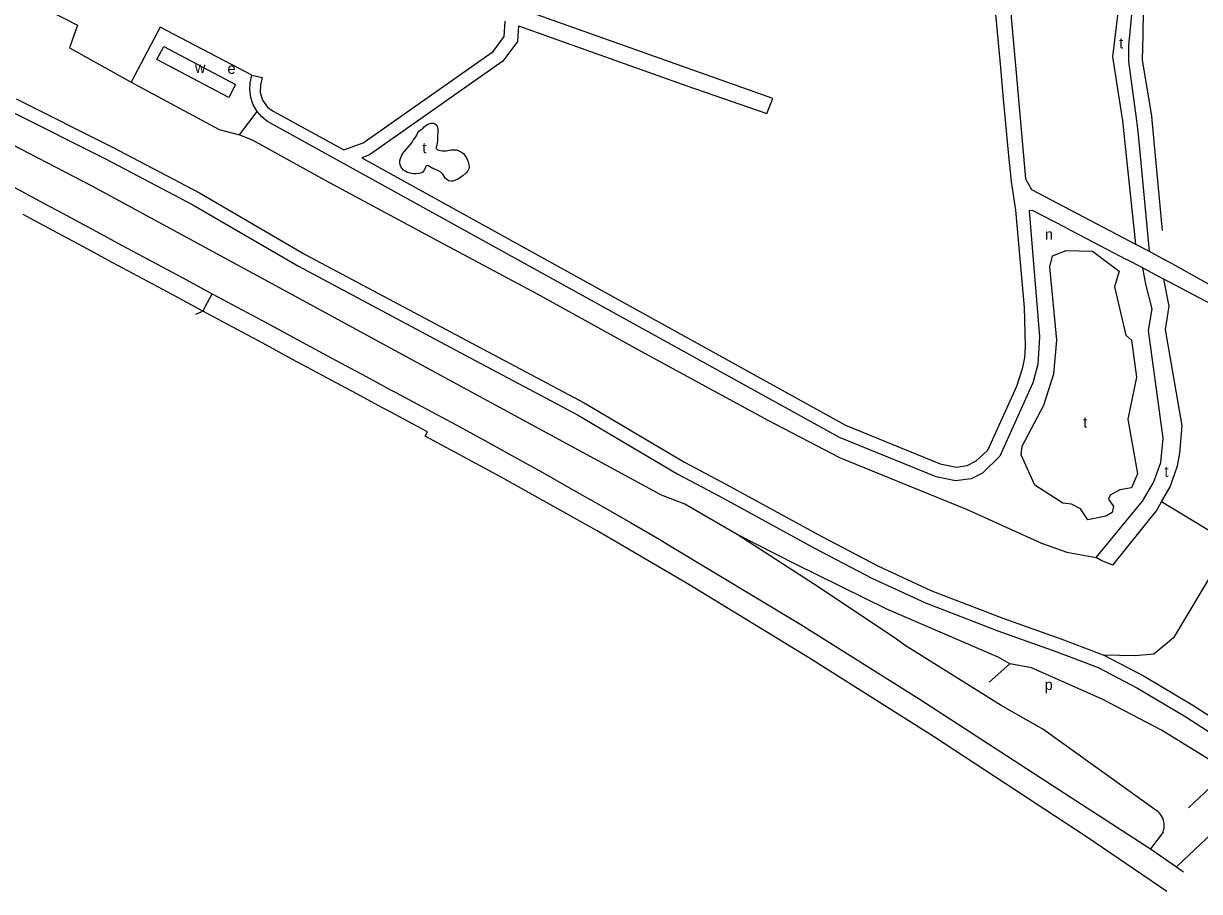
# Model space of a CAD drawing. Extents: x 156521 to 159067, y 384230 to 386095.
# Drawn here: x 157935.8 to 158368, y 384229.6 to 384548.6 of the extents above; entities that cross this region are included whole.
import ezdxf

# ---------------------------------------------------------------- set-up
doc = ezdxf.new("R2010")
doc.units = 0
for name, color, linetype in [('BLT_Basislijn', 7, 'Continuous'), ('BLT_Bebouwing', 7, 'Continuous'), ('BLT_Centroide', 7, 'Continuous'), ('BLT_Vlakafsluiter', 7, 'Continuous')]:
    doc.layers.add(name, color=color, linetype=linetype)

msp = doc.modelspace()

# ---------------------------------------------------------------- linework, layer by layer
at = {"layer": 'BLT_Basislijn'}
for p, q in [((158117.73, 384547.76), (158179.61, 384525.76)), ((158179.61, 384525.76), (158208.95, 384515.59)), ((158208.95, 384515.59), (158211.14, 384521.03)), ((158015.26, 384507.7), (158021.69, 384516.29)), ((158341.02, 384500), (158344.49, 384467.52)), ((158346.19, 384500), (158349.48, 384464.94)), ((158351.73, 384500), (158354.29, 384472.55)), ((158318.77, 384473.66), (158341.17, 384461.95)), ((158344.49, 384467.52), (158349.48, 384464.94)), ((158349.48, 384464.94), (158355.23, 384461.76)), ((158347.14, 384458.83), (158341.17, 384461.95)), ((158347.14, 384458.83), (158354.81, 384454.73)), ((158359.21, 384459.6), (158355.23, 384461.76)), ((158379.14, 384357.53), (158354.03, 384372.8)), ((158298.23, 384313.32), (158290.65, 384306.61)), ((158354.57, 384251.49), (158349.98, 384245.32)), ((158349.98, 384245.32), (158359.46, 384238.69)), ((158359.46, 384238.69), (158362.05, 384236.88))]:
    msp.add_line(p, q, dxfattribs=at)
for points in [[(158347.66, 384764.32), (158339.46, 384719.87), (158343.84, 384696.55), (158347.85, 384681.86), (158351.83, 384649.2), (158353.59, 384632.21), (158356.38, 384617.88), (158354.82, 384603.49), (158346.38, 384581.08), (158344.02, 384563.34), (158341.93, 384540.55), (158341.93, 384534.62), (158344.71, 384513.8)], [(158338.18, 384750.37), (158332.73, 384727.08), (158332.09, 384716.25), (158341.82, 384681.91), (158348.18, 384632.49), (158351.29, 384618.67), (158349.25, 384604.76), (158341.64, 384583.18), (158336, 384536.38), (158339.65, 384512.85)], [(158349.3, 384748.74), (158349.57, 384749.87), (158346.07, 384730.07), (158345.98, 384718.2), (158347.05, 384711.7), (158354.51, 384675.52), (158356.23, 384662.18), (158363.02, 384616.76), (158362.4, 384605.81), (158350.04, 384571.75), (158348.53, 384564.28), (158347.29, 384553.51), (158347.11, 384544.39)], [(158063.68, 384682.82), (158091.35, 384674.28), (158289.38, 384611.66), (158289.94, 384611.22), (158289.44, 384598.2), (158289.79, 384586.23), (158294.7, 384533.65)], [(157759.09, 384652.69), (157782.61, 384640.14), (157822.65, 384618.48), (157861.04, 384598.05), (157900.93, 384576.11), (157955.64, 384548.01), (157952.77, 384539.68), (157975.42, 384527.13)], [(158296.83, 384613.3), (158296.16, 384593.77), (158298.73, 384550.78), (158300.43, 384531.85)], [(158211.14, 384521.03), (158119.09, 384553.8), (158091.69, 384563.28)], [(158019.73, 384529.6), (158023.57, 384528.75), (158022.98, 384526.07), (158022.84, 384523.29), (158023.65, 384520.45), (158025.5, 384517.9), (158027.61, 384516.41), (158053.57, 384502.16), (158060.59, 384504.78), (158108.47, 384538.37), (158112.43, 384543.81), (158112.84, 384549.5)], [(158019.73, 384529.6), (157986.08, 384547.34), (157975.42, 384527.13)], [(158117.73, 384547.76), (158117.31, 384542.02), (158112.03, 384534.76), (158062.94, 384500.32), (158060.12, 384499.27), (158237.83, 384401.04), (158272.65, 384386.87), (158278.5, 384385.61), (158282.54, 384386.16), (158285.9, 384387.89), (158290.1, 384391.65)], [(158347.11, 384544.39), (158346.94, 384535.26), (158350.36, 384514.6), (158351.73, 384500)], [(158198.13, 384360.81), (158178.88, 384371.96), (158170.28, 384375.33), (158099.16, 384413.93), (158028.59, 384452.22), (157961.03, 384488.81), (157869.57, 384536.26)], [(158294.7, 384533.65), (158295.88, 384520.92), (158297.84, 384500)], [(158021.69, 384516.29), (158020.23, 384518.8), (158019.34, 384521.46), (158018.99, 384524.25), (158019.16, 384526.86), (158019.73, 384529.6)], [(158300.43, 384531.85), (158303.29, 384500)], [(157975.42, 384527.13), (158007.71, 384509.66), (158015.26, 384507.7)], [(157933.17, 384520.95), (157968.51, 384503.22), (158000.47, 384486.36), (158039.37, 384463.8), (158100.54, 384431.13), (158141.86, 384409.2), (158178.73, 384387.41), (158193.92, 384379.3), (158229.14, 384360.05), (158249.76, 384349.3), (158269.22, 384340.32), (158295.66, 384330.08), (158317.32, 384322.35), (158332.84, 384316.5)], [(157930.85, 384516.53), (157966.23, 384498.78), (157998.05, 384481.98), (158036.93, 384459.43), (158098.19, 384426.71), (158139.42, 384404.83), (158176.28, 384383.04), (158191.55, 384374.9), (158226.78, 384355.64), (158247.56, 384344.81), (158267.27, 384335.72), (158293.91, 384325.39), (158315.6, 384317.66), (158330.79, 384311.93), (158345.17, 384304.36), (158362.89, 384293.81), (158376.39, 384285.18), (158390.18, 384274.78), (158399.69, 384267.38)], [(158294.55, 384389.58), (158288.18, 384383.44), (158284.06, 384381.32), (158278.31, 384380.54), (158271.17, 384382.07), (158235.67, 384396.52), (158025.55, 384512.66), (158023.44, 384514.3), (158021.69, 384516.29)], [(158339.65, 384512.85), (158341.02, 384500)], [(158344.71, 384513.8), (158345.36, 384508.91), (158346.19, 384500)], [(158015.26, 384507.7), (158019.88, 384505.9), (158047.79, 384490.4), (158086.73, 384469.44), (158124.57, 384449.24), (158162.93, 384428.06), (158189.46, 384413.58), (158209.37, 384402.89), (158235.65, 384389.08), (158257.02, 384380.46), (158282.63, 384370.07), (158309.87, 384357.63), (158319.19, 384354.3), (158330.03, 384352.44)], [(158297.84, 384500), (158298.72, 384490.56), (158299.87, 384483.23)], [(158303.29, 384500), (158304.04, 384491.58), (158306.24, 384487.66), (158344.49, 384467.52)], [(157928.09, 384490.78), (157939.1, 384484.86), (157943.44, 384482.53), (157950.11, 384478.94), (157961.12, 384473.02), (157972.12, 384467.1), (157983.13, 384461.18), (157994.14, 384455.26), (158005.15, 384449.34)], [(158299.87, 384483.23), (158300.4, 384480.01), (158303.48, 384444.32), (158303.96, 384430.04), (158303.69, 384425.74), (158302.81, 384421.78), (158300.76, 384415.21), (158290.1, 384391.65)], [(158001.72, 384442.95), (157990.71, 384448.87), (157979.7, 384454.79), (157968.69, 384460.71), (157957.68, 384466.63), (157946.67, 384472.55), (157940, 384476.14), (157935.66, 384478.47)], [(158318.77, 384473.66), (158306.61, 384479.96), (158305.41, 384479.83), (158309.21, 384433.5), (158308.61, 384423.32), (158306.75, 384416.54), (158294.55, 384389.58)], [(158330.03, 384352.44), (158347.02, 384373.15), (158351.01, 384379.98), (158353.71, 384387.25), (158354.61, 384396.29), (158349.17, 384435.85), (158350.52, 384443.83), (158348.27, 384452.84), (158347.14, 384458.83)], [(158391.54, 384442.78), (158382.68, 384446.47), (158359.21, 384459.6)], [(158354.03, 384372.8), (158357.21, 384378.34), (158359.86, 384386.03), (158360.79, 384390.68), (158361.61, 384400.82), (158355.53, 384436.21), (158356.84, 384444.75), (158354.81, 384454.73)], [(158388.72, 384437.21), (158385.22, 384438.59), (158354.81, 384454.73)], [(158005.15, 384449.34), (158016.16, 384443.42), (158027.17, 384437.49), (158038.18, 384431.57), (158049.19, 384425.65), (158055.97, 384422.01), (158060.2, 384419.73), (158071.21, 384413.81), (158072.62, 384413.05), (158082.21, 384407.89), (158085.93, 384405.89), (158093.24, 384401.95), (158104.24, 384395.96), (158115.22, 384389.91), (158126.17, 384383.82), (158126.37, 384383.71), (158137.09, 384377.68), (158147.98, 384371.49), (158158.85, 384365.24), (158169.69, 384358.95), (158173.88, 384356.49), (158221.42, 384327.75), (158264.96, 384300.4), (158318.39, 384265.76), (158349.98, 384245.32)], [(158083.44, 384397), (158084.33, 384398.52), (158082.49, 384399.51), (158078.78, 384401.51), (158069.19, 384406.66), (158067.77, 384407.43), (158056.76, 384413.35), (158052.53, 384415.62), (158045.75, 384419.27), (158034.74, 384425.19), (158023.74, 384431.11), (158012.73, 384437.03), (158001.72, 384442.95)], [(158326.41, 384249.68), (158270.21, 384286.65), (158224.65, 384315.38), (158180.33, 384342.47), (158146.68, 384362.16), (158111.38, 384381.86), (158083.44, 384397)], [(158336.07, 384349.61), (158352.18, 384369.58), (158354.03, 384372.8)], [(158256.6, 384322.32), (158228.59, 384341.13), (158198.13, 384360.81)], [(158298.23, 384313.32), (158293.96, 384315.81), (158253.03, 384333.4), (158219.55, 384349.91), (158198.13, 384360.81)], [(158379.14, 384357.53), (158358.37, 384322.88), (158351.24, 384316.92), (158344.38, 384316.23), (158332.84, 384316.5)], [(158336.07, 384349.61), (158335.72, 384349.66), (158331.84, 384351.3), (158330.03, 384352.44)], [(158295.14, 384298.02), (158259.87, 384319.99), (158256.6, 384322.32)], [(158332.84, 384316.5), (158347.62, 384308.73), (158365.52, 384298.06), (158379.25, 384289.29), (158393.22, 384278.75), (158403.13, 384271.03), (158406.63, 384269.51)], [(158363.96, 384260.34), (158376.01, 384271.73), (158376.42, 384273.48), (158376.02, 384275.36), (158353.95, 384288.95), (158332.21, 384300.36), (158306.22, 384311.84), (158298.23, 384313.32)], [(158351.6, 384259.78), (158310.41, 384289.27), (158295.14, 384298.02)], [(158399.69, 384267.38), (158394.76, 384265.44), (158384.48, 384260.27), (158376.97, 384255.3), (158359.46, 384238.69)], [(158354.57, 384251.49), (158354.79, 384252.19), (158354.93, 384252.92), (158354.99, 384253.66), (158354.97, 384254.4), (158354.88, 384255.13), (158354.7, 384255.85), (158354.45, 384256.55), (158354.12, 384257.21), (158353.72, 384257.84), (158353.26, 384258.42), (158352.74, 384258.95), (158352.17, 384259.41), (158351.6, 384259.78)], [(158355.92, 384229.65), (158326.41, 384249.68)]]:
    msp.add_lwpolyline(points, dxfattribs=at)
for points in [[(158074.33, 384498.99), (158074.86, 384500.21), (158075.24, 384500.81), (158076.35, 384502.22), (158077.85, 384503.91), (158078.49, 384504.76), (158079.07, 384505.73), (158079.78, 384506.6), (158080.36, 384507.63), (158080.74, 384508.57), (158081.09, 384509.07), (158081.96, 384509.65), (158082.43, 384509.9), (158082.57, 384510.01), (158083.01, 384510.66), (158084.06, 384511.38), (158084.78, 384511.71), (158085.63, 384512.02), (158086.45, 384512.01), (158086.99, 384511.81), (158087.54, 384511.35), (158087.97, 384510.48), (158088.11, 384509.7), (158088.02, 384506.17), (158087.98, 384505.53), (158087.69, 384503.93), (158087.49, 384503.22), (158087.46, 384502.75), (158087.6, 384502.57), (158087.89, 384502.34), (158088.42, 384502.07), (158089.68, 384501.79), (158091.16, 384501.87), (158092.89, 384502.17), (158094.17, 384502.26), (158095.08, 384502.15), (158096.8, 384501.39), (158097.47, 384500.84), (158098.6, 384499.32), (158099.11, 384498.16), (158099.51, 384496.75), (158099.57, 384495.97), (158099.45, 384495.18), (158099.11, 384494.47), (158098.64, 384493.86), (158097.44, 384492.8), (158095.68, 384491.5), (158094.32, 384490.9), (158093.73, 384490.75), (158092.93, 384490.68), (158092.02, 384490.84), (158091.34, 384491.27), (158090.82, 384491.85), (158089.92, 384493.28), (158089.2, 384493.98), (158088.38, 384494.46), (158086.29, 384495.3), (158085.58, 384495.67), (158084.36, 384496.41), (158083.96, 384496.34), (158083.73, 384496.2), (158083.66, 384496.13), (158083.13, 384494.94), (158082.57, 384494.05), (158082.03, 384493.7), (158081.24, 384493.47), (158079.97, 384493.42), (158079.18, 384493.44), (158077.94, 384493.57), (158076.93, 384493.84), (158075.43, 384494.72), (158074.82, 384495.42), (158074.48, 384496.02), (158074.24, 384496.75), (158074.15, 384497.5), (158074.17, 384498.2)], [(158313.93, 384463.31), (158319, 384465.21), (158328.69, 384464.96), (158338.39, 384457.67), (158336.68, 384451.84), (158340.86, 384434.11), (158342.95, 384432.21), (158344.78, 384418.65), (158341.68, 384403.19), (158345.23, 384383.11), (158343.01, 384378.04), (158338.7, 384377.22), (158335.09, 384375.26), (158334.58, 384373.8), (158336.36, 384371.08), (158335.91, 384368.92), (158333.57, 384367.53), (158326.98, 384366.2), (158324.26, 384370.32), (158320.9, 384372.03), (158317.8, 384372.41), (158307.47, 384378.99), (158302.4, 384390.08), (158302.78, 384393.25), (158310.77, 384408.32), (158314.38, 384419.85), (158315.58, 384432.27), (158312.92, 384459.19)]]:
    msp.add_lwpolyline(points, close=True, dxfattribs=at)
at = {"layer": 'BLT_Bebouwing'}
msp.add_lwpolyline([(157987.37, 384540.14), (158013.76, 384526.22), (158011.26, 384521.48), (157984.87, 384535.4)], close=True, dxfattribs=at)
at = {"layer": 'BLT_Vlakafsluiter'}
for p, q in [((158001.72, 384442.95), (158005.15, 384449.34)), ((157999.19, 384441.81), (158001.72, 384442.95))]:
    msp.add_line(p, q, dxfattribs=at)

# ---------------------------------------------------------------- texts
at = {"layer": 'BLT_Centroide'}
for s, p in [('t', (158338.44, 384539.47)), ('w', (157998.85, 384530.49)), ('e', (158010.79, 384530.12)), ('t', (158082.41, 384500.97)), ('n', (158311.15, 384469.14)), ('t', (158325.21, 384400.09)), ('t', (158355.07, 384382.03)), ('p', (158311.08, 384303.69))]:
    msp.add_text(s, height=4, dxfattribs=at).set_placement(p)

doc.saveas('drawing.dxf')
